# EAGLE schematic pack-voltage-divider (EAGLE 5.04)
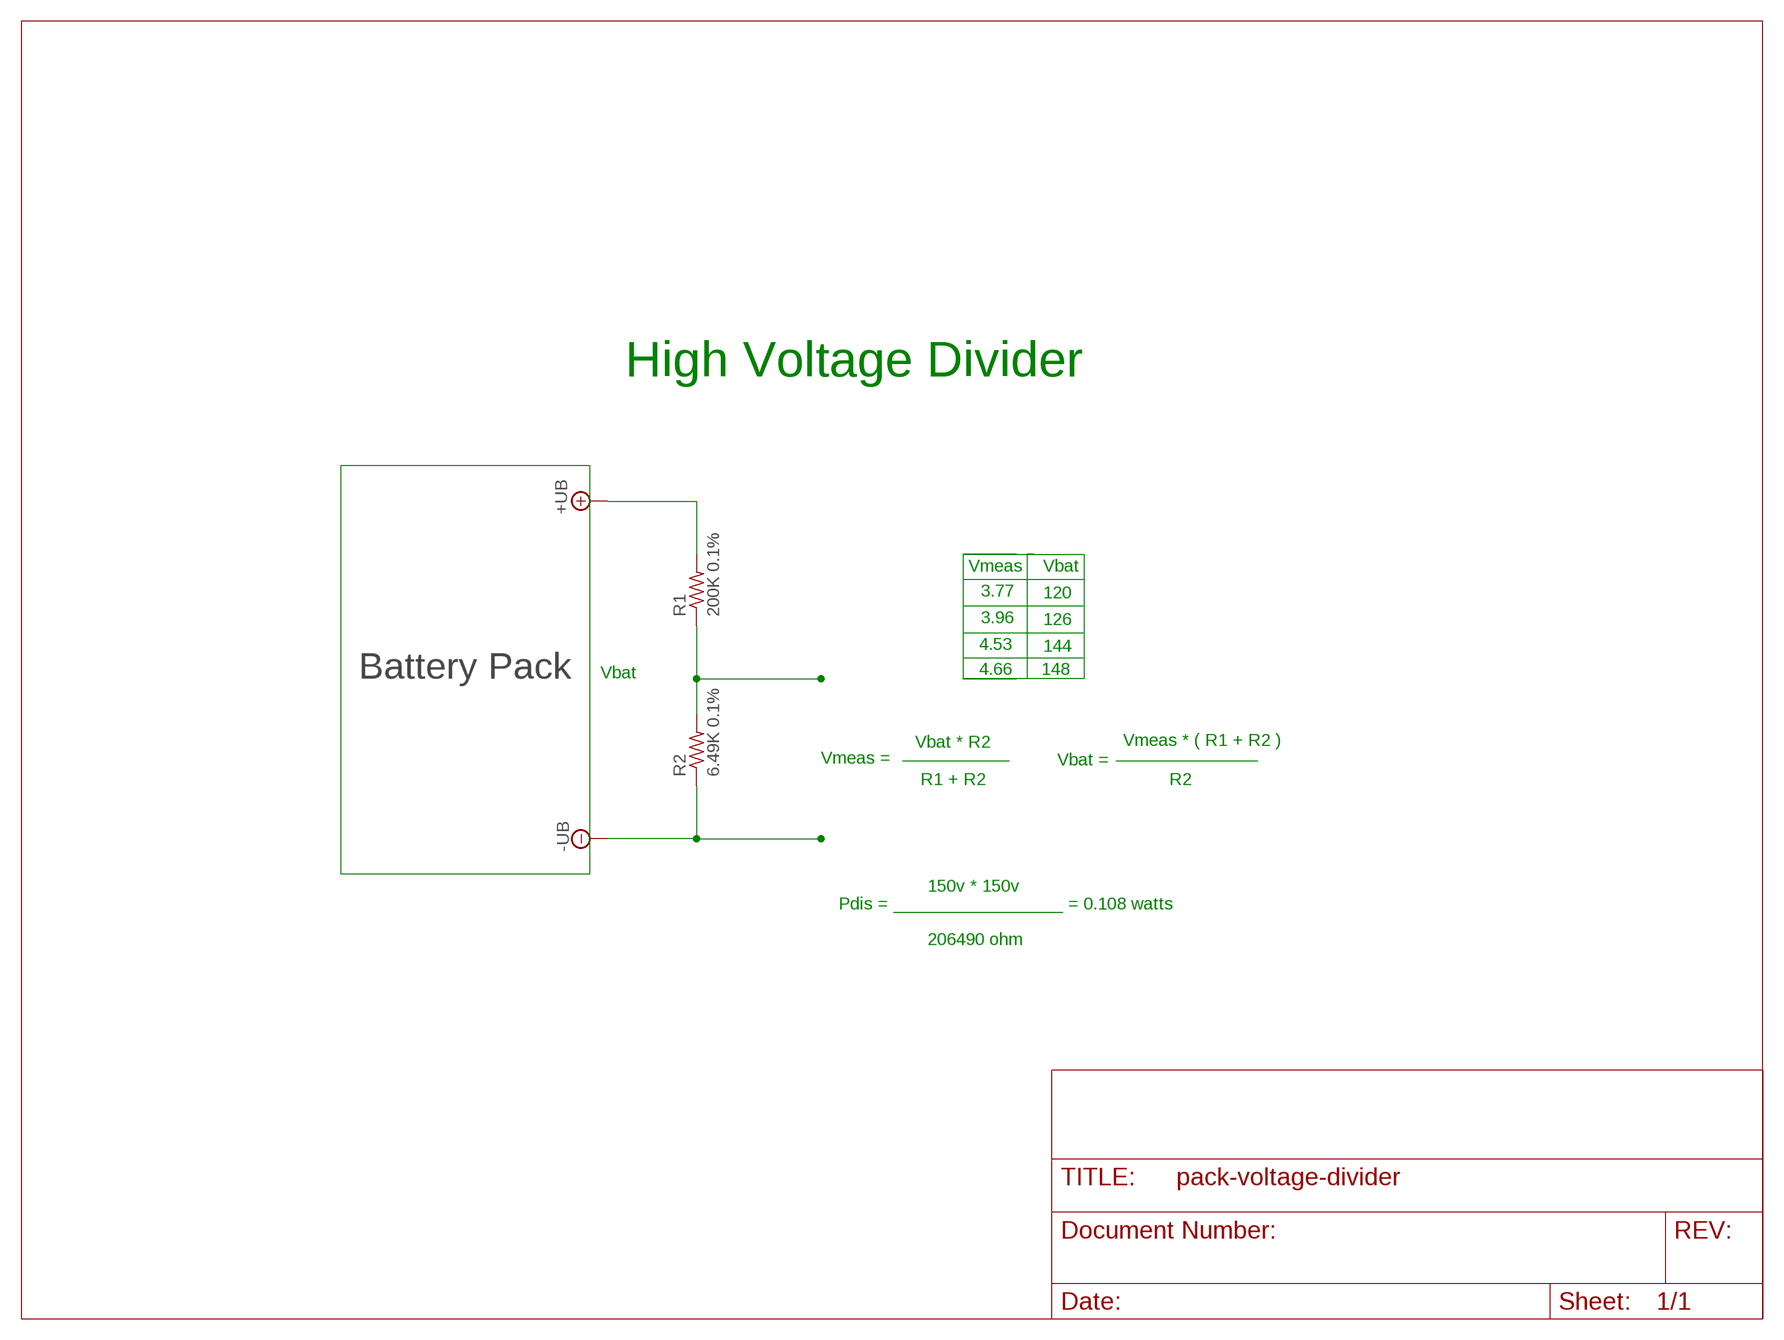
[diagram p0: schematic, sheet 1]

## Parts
R1  200K 0.1%  R-US_R0805  [R0805]
R2  6.49K 0.1%  R-US_R0402  [R0402]

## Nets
+UB: R1.2
-UB: R2.1
N$2: R1.1 R2.2

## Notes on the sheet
- High Voltage Divider
- Vmeas | Vbat
- 3.77 | 120
- 3.96 | 126
- 4.53 | 144
- Battery Pack | Vbat | 4.66 | 148
- Vbat * R2 | Vmeas * ( R1 + R2 )
- Vmeas = | Vbat =
- R1 + R2 | R2
- 150v * 150v
- Pdis = _________________ = 0.108 watts
- 206490 ohm

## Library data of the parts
R1 R2 = resistor:R-US_: RESISTOR, American symbol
